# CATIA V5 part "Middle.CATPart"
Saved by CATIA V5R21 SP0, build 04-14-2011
Part number: Part1.1
Material "Gold Metal": density 7860 kg/m3, Young's modulus 2e+11 Pa, Poisson ratio 0.266
Bounding box of the stored display mesh (mm): x 0 to 10, y -25 to 0, z 0 to 51.4
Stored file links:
  G:\CATIA\Class\Project_2\Middle.CATPart
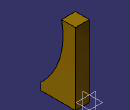
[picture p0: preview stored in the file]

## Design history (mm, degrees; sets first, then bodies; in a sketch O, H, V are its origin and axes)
Body1 (main body), material "Gold Metal"
  Sketch1 on yz-plane, origin (0, 0, 0), H (0, 1, 0), V (0, 0, 1)
    line L1 (0, 0) -> (-25, 0)
    line L2 (-25, 0) -> (-25, 5)
    arc A1 centre (-59.0357, 41.6275) radius 50 from (-25, 5) to (-10, 51.4) ccw
    line L3 (-10, 51.4) -> (0, 51.4)
    point P5 (0, 51.4)
    line L4 (0, 51.4) -> (0, 0)
    length L1 = 25
    length L3 = 10
    length L4 = 51.4
    radius A1 = 50
    length L2 = 5
    horizontal: L1 H, L3 H
    vertical: L2 V, L4 V
    coincidence: P5 V
  Pad1: profile Sketch1, direction (1, 0, 0), length 10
